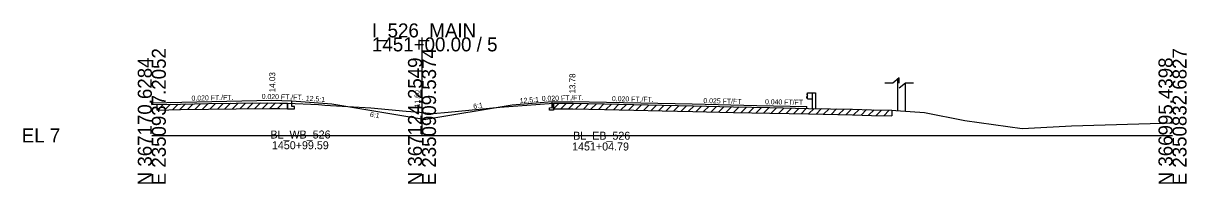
# Model space of a CAD drawing. Extents: x -170 to 2527928, y -10 to 1619750.
# Drawn here: x 5974.3 to 6206.8, y -9.7 to 22.5 of the extents above; entities that cross this region are included whole.
import ezdxf

# ---------------------------------------------------------------- set-up
doc = ezdxf.new("R2010")
doc.units = 0
for name, color, linetype in [('Default', 7, 'Continuous'), ('RD_GPK_XS_Cell', 7, 'Continuous'), ('RD_PD_NOISE-WALL-GM', 7, 'Continuous'), ('RD_XS_Base', 7, 'Continuous'), ('RD_XS_EarthShd', 7, 'Continuous'), ('RD_XS_ExGround', 7, 'Continuous'), ('RD_XS_ExPaveRet', 7, 'Continuous'), ('RD_XS_GR', 7, 'Continuous'), ('RD_XS_Pave', 7, 'Continuous'), ('RD_XS_PaveShd', 7, 'Continuous'), ('RD_XS_TieSlope', 7, 'Continuous'), ('RD_XS_TX_Elev_EX', 7, 'Continuous'), ('RD_XS_TX_Slope', 7, 'Continuous'), ('RD_XS_TX_Station', 7, 'Continuous')]:
    doc.layers.add(name, color=color, linetype=linetype)

msp = doc.modelspace()

# ---------------------------------------------------------------- linework, layer by layer
at = {"layer": 'Default'}
for p, q in [((6148.1, 10.49), (6146.52, 10.49)), ((6149.35, 11.52), (6148.1, 10.49)), ((6149.35, 10.49), (6149.35, 11.52)), ((6150.6, 10.49), (6149.35, 9.47)), ((6152.2, 10.49), (6150.6, 10.49))]:
    msp.add_line(p, q, dxfattribs=at)
at = {"layer": 'RD_GPK_XS_Cell'}
for p, q in [((6054, 0), (6054, 19.64)), ((6000, 0), (6054, 0)), ((6054, 0), (6204, 0))]:
    msp.add_line(p, q, dxfattribs=at)
at = {"layer": 'RD_PD_NOISE-WALL-GM'}
for p, q in [((6149.1, 4.93), (6149.1, 11.31)), ((6150.6, 4.81), (6150.6, 10.49))]:
    msp.add_line(p, q, dxfattribs=at)
at = {"layer": 'RD_XS_Base'}
for p, q in [((6027.12, 5.33), (6027.12, 6.47)), ((6027.12, 5.33), (6028.5, 5.3)), ((6028, 5.81), (6028, 6.95)), ((6028.5, 5.8), (6028, 5.81)), ((6028.5, 5.3), (6028.5, 5.8)), ((6079.5, 5.55), (6080, 5.56)), ((6079.5, 5.05), (6079.5, 5.55)), ((6080.27, 5.07), (6079.5, 5.05)), ((6080, 5.56), (6080, 6.7)), ((6080.27, 6.46), (6080.27, 5.07)), ((6130.89, 5.43), (6130.89, 5.79))]:
    msp.add_line(p, q, dxfattribs=at)
at = {"layer": 'RD_XS_EarthShd'}
for p, q in [((6028, 6.95), (6036, 6.31)), ((6080, 6.7), (6072, 6.06))]:
    msp.add_line(p, q, dxfattribs=at)
at = {"layer": 'RD_XS_ExGround'}
msp.add_lwpolyline([(6000, 6.18), (6005.72, 6.29), (6011.35, 6.39), (6016.83, 6.45), (6023.84, 6.55), (6025.59, 6.49), (6027.12, 6.47), (6033.29, 6.16), (6033.95, 6.13), (6034.55, 6.09), (6043.77, 5.5), (6050.82, 4.88), (6053.56, 4.64), (6054, 4.6), (6056.22, 4.41), (6059.23, 4.68), (6069.53, 5.67), (6076.78, 6.22), (6080.27, 6.46), (6082.15, 6.45), (6084.17, 6.45), (6090.46, 6.3), (6096.32, 6.16), (6102.03, 6.05), (6108.12, 5.93), (6116.24, 5.74), (6123.55, 5.56), (6131.22, 5.42), (6140.03, 5.26), (6143.85, 5.14), (6147.88, 5.03), (6148.7, 4.96), (6154.43, 4.58), (6162.46, 3), (6173.94, 1.38), (6177.7, 1.61), (6183.8, 1.94), (6204, 2.52)], dxfattribs=at)
at = {"layer": 'RD_XS_ExPaveRet'}
for p, q in [((6001.1, 5.08), (6002.24, 6.22)), ((6001.1, 5.08), (6001.1, 6.2)), ((6001.1, 5.08), (6005.72, 5.16)), ((6002.6, 5.11), (6003.74, 6.25)), ((6004.1, 5.13), (6005.24, 6.28)), ((6005.6, 5.16), (6006.74, 6.3)), ((6005.72, 5.16), (6011.35, 5.27)), ((6007.1, 5.19), (6008.24, 6.33)), ((6008.6, 5.22), (6009.74, 6.36)), ((6010.1, 5.24), (6011.24, 6.39)), ((6011.35, 5.27), (6016.83, 5.33)), ((6011.6, 5.27), (6012.74, 6.4)), ((6013.1, 5.29), (6014.24, 6.42)), ((6014.6, 5.31), (6015.74, 6.44)), ((6016.1, 5.32), (6017.24, 6.46)), ((6016.83, 5.33), (6023.84, 5.42)), ((6017.6, 5.34), (6018.74, 6.48)), ((6019.1, 5.36), (6020.24, 6.5)), ((6020.6, 5.38), (6021.74, 6.52)), ((6022.1, 5.4), (6023.24, 6.54)), ((6023.6, 5.42), (6024.7, 6.52)), ((6023.84, 5.42), (6025.59, 5.37)), ((6025.1, 5.39), (6026.2, 6.48)), ((6025.59, 5.37), (6027.12, 5.34)), ((6027.12, 6.47), (6027.12, 5.34)), ((6080.27, 5.34), (6080.27, 6.46)), ((6080.27, 5.34), (6081.39, 6.45)), ((6080.27, 5.34), (6082.15, 5.33)), ((6081.77, 5.33), (6082.89, 6.45)), ((6082.15, 5.33), (6084.17, 5.33)), ((6083.27, 5.33), (6084.38, 6.45)), ((6084.17, 5.33), (6090.46, 5.18)), ((6084.77, 5.32), (6085.86, 6.41)), ((6086.27, 5.28), (6087.36, 6.38)), ((6087.77, 5.24), (6088.86, 6.34)), ((6089.27, 5.21), (6090.36, 6.3)), ((6090.46, 5.18), (6096.32, 5.03)), ((6090.77, 5.17), (6091.86, 6.27)), ((6092.27, 5.13), (6093.36, 6.23)), ((6093.77, 5.1), (6094.86, 6.19)), ((6095.27, 5.06), (6096.36, 6.15)), ((6096.32, 5.03), (6102.03, 4.93)), ((6096.77, 5.03), (6097.87, 6.13)), ((6098.27, 5), (6099.37, 6.1)), ((6099.77, 4.97), (6100.87, 6.07)), ((6101.27, 4.94), (6102.37, 6.04)), ((6102.03, 4.93), (6108.12, 4.81)), ((6102.77, 4.91), (6103.87, 6.01)), ((6104.27, 4.88), (6105.37, 5.98)), ((6105.77, 4.86), (6106.87, 5.95)), ((6107.27, 4.83), (6108.37, 5.92)), ((6108.12, 4.81), (6116.24, 4.61)), ((6108.77, 4.79), (6109.86, 5.89)), ((6110.27, 4.76), (6111.36, 5.85)), ((6111.77, 4.72), (6112.86, 5.82)), ((6113.27, 4.69), (6114.36, 5.78)), ((6114.77, 4.65), (6115.86, 5.75)), ((6116.27, 4.61), (6117.36, 5.71)), ((6117.77, 4.58), (6118.86, 5.67)), ((6119.27, 4.54), (6120.36, 5.64)), ((6120.77, 4.51), (6121.86, 5.6)), ((6122.27, 4.47), (6123.36, 5.56)), ((6123.77, 4.43), (6124.87, 5.54)), ((6125.27, 4.41), (6126.37, 5.51)), ((6126.77, 4.38), (6127.87, 5.48)), ((6128.27, 4.35), (6129.37, 5.45)), ((6129.77, 4.32), (6130.87, 5.43)), ((6131.27, 4.3), (6132.37, 5.4)), ((6132.77, 4.27), (6133.87, 5.37)), ((6134.27, 4.24), (6135.37, 5.34)), ((6135.77, 4.21), (6136.87, 5.32)), ((6137.27, 4.19), (6138.37, 5.29)), ((6138.77, 4.16), (6139.87, 5.26)), ((6140.27, 4.13), (6141.36, 5.22)), ((6141.77, 4.08), (6142.86, 5.17)), ((6143.27, 4.04), (6144.36, 5.13)), ((6144.77, 4), (6145.86, 5.09)), ((6146.27, 3.95), (6147.36, 5.04)), ((6147.88, 5.03), (6147.88, 3.91)), ((6116.24, 4.61), (6123.55, 4.44)), ((6123.55, 4.44), (6131.22, 4.3)), ((6131.22, 4.3), (6140.03, 4.14)), ((6140.03, 4.14), (6143.85, 4.02)), ((6143.85, 4.02), (6147.88, 3.91))]:
    msp.add_line(p, q, dxfattribs=at)
at = {"layer": 'RD_XS_GR'}
for p, q in [((6131.06, 8.44), (6130.89, 8.24)), ((6130.89, 8.24), (6130.89, 8.19)), ((6130.89, 8.19), (6131.06, 7.99)), ((6130.89, 7.67), (6131.06, 7.87)), ((6130.89, 7.62), (6130.89, 7.67)), ((6131.06, 7.42), (6130.89, 7.62)), ((6131.06, 7.34), (6131.06, 8.51)), ((6131.06, 8.51), (6131.97, 8.51)), ((6131.06, 7.34), (6131.97, 7.34)), ((6131.97, 8.51), (6132.64, 8.51)), ((6131.97, 8.51), (6131.97, 5.42)), ((6132.64, 8.51), (6132.64, 5.4))]:
    msp.add_line(p, q, dxfattribs=at)
at = {"layer": 'RD_XS_Pave'}
for p, q in [((6000, 6.55), (6024, 7.03)), ((6084, 6.78), (6108, 6.3)), ((6108, 6.3), (6120.89, 5.97))]:
    msp.add_line(p, q, dxfattribs=at)
at = {"layer": 'RD_XS_PaveShd'}
for p, q in [((6024, 7.03), (6028, 6.95)), ((6000, 6.18), (6000, 6.55)), ((6080, 6.7), (6084, 6.78)), ((6120.89, 5.97), (6130.89, 5.79))]:
    msp.add_line(p, q, dxfattribs=at)
at = {"layer": 'RD_XS_TieSlope'}
for p in [(6036, 6.31), (6072, 6.06)]:
    msp.add_line(p, (6054.75, 3.19), dxfattribs=at)

# ---------------------------------------------------------------- texts
at = {"layer": 'RD_GPK_XS_Cell'}
for s, p in [('I_526_MAIN', (6044, 19.64)), ('1451+00.00 / 5', (6044, 16.84)), ('EL 7', (5974, -1.4))]:
    msp.add_text(s, height=2.8, dxfattribs=at).set_placement(p)
for s, p in [('E 2350937.2052', (6002.8, -10)), ('E 2350909.5374', (6056.8, -10)), ('E 2350832.6827', (6206.8, -10)), ('N 367170.6284', (6000, -10)), ('N 367124.2549', (6054, -10)), ('N 366995.4398', (6204, -10))]:
    msp.add_text(s, height=2.8, rotation=90, dxfattribs=at).set_placement(p)
at = {"layer": 'RD_XS_TX_Elev_EX'}
msp.add_text('11.60', height=1, rotation=90, dxfattribs=at).set_placement((6053.5, 5.6))
at = {"layer": 'RD_XS_TX_Slope'}
for s, rotation, p in [('0.020 FT./FT.', 1.1458, (6007.94, 6.96)), ('0.020 FT./FT.', 358.8542, (6021.95, 7.32)), ('12.5:1', 355.4261, (6030.75, 6.99)), ('12.5:1', 4.5739, (6073.58, 6.44)), ('0.020 FT./FT.', 1.1458, (6077.94, 6.91)), ('0.020 FT./FT.', 358.8542, (6091.95, 6.87)), ('0.025 FT/FT', 358.5427, (6110.23, 6.49)), ('0.040 FT/FT', 359.1102, (6122.55, 6.25)), ('6:1', 350.5446, (6043.54, 3.74)), ('6:1', 9.4623, (6064.33, 5.31))]:
    msp.add_text(s, height=1, rotation=rotation, dxfattribs=at).set_placement(p)
at = {"layer": 'RD_XS_TX_Station'}
for s, p in [(' 14.03', (6024.66, 8.2)), (' 13.78', (6084.66, 7.95))]:
    msp.add_text(s, height=1.2, rotation=90, dxfattribs=at).set_placement(p)
for s, p in [('BL_WB_526', (6023.71, -0.62)), ('BL_EB_526', (6084.2, -0.86)), ('1450+99.59', (6024, -2.77)), ('1451+04.79', (6084, -3.02))]:
    msp.add_text(s, height=1.6, dxfattribs=at).set_placement(p)

doc.saveas('drawing.dxf')
